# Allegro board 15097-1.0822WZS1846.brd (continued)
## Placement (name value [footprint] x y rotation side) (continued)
C553  SCD1U50V3KX-DL-GP  [C603H35]  137.88 90.2 180 bottom
C554  SCD1U50V3KX-DL-GP  [C603H35]  145.98 108.38 90 bottom
C555  SCD1U50V3KX-DL-GP  [C603H35]  141.23 43.38 180 bottom
C556  SCD1U50V3KX-DL-GP  [C603H35]  93.02 37.49 180 bottom
C557  SCD1U50V3KX-DL-GP  [C603H35]  89.14 37.47 180 bottom
C558  SCD1U50V3KX-DL-GP  [C603H35]  51.9 52.04 0 bottom
C559  SCD1U50V3KX-DL-GP  [C603H35]  36.41 44.93 180 bottom
C560  SCD1U50V3KX-DL-GP  [C603H35]  25.28 67.51 90 bottom
C561  SCD1U50V3KX-DL-GP  [C603H35]  45.63 223.09 270 bottom
C562  SCD1U50V3KX-DL-GP  [C603H35]  72.07 223.27 90 bottom
C563  SCD1U50V3KX-DL-GP  [C603H35]  157.07 71.2 270 bottom
C564  SC1U10V2KX-1DLGP  [C402H22]  163.24 139.82 90 bottom
C565  SC10U10V5KX-2DLGP  [C805H50]  160.67 150.07 0 bottom
C568  SCD1U16V2KX-3DLGP  [C402H22]  161.18 131.35 270 bottom
C569  SC1U10V2KX-1DLGP  [C402H22]  28.74 181.48 270 top
CMCLR2  JOWLE-CON2-5-GP  [A2541WV0-1EX2PA-6T]  147 178 270 top
CONVT1  CLX-CON10-10-GP  [CI1410M1HRL-NH]  25 36.65 270 top
CPU1  APOLLO-LAKE-GP  [BGA1296M3124H56]  83 165 270 top
D1  1SS355-4-GP  [SOD323AKH38]  17.25 202.67 180 top
D2  BAT54A-7-F-2-GP  [SOT23-2D4-312H48]  146.27 192 0 top
D3  BAT54A-7-F-2-GP  [SOT23-2D4-312H48]  100.01 103.4 90 top
D4  BAT54A-7-F-2-GP  [SOT23-2D4-312H48]  124.63 70.92 0 top
D5  BAV99GP-GP  [SOT23-2D4-312H48]  45.4 29.59 90 top
D6  1SS355-4-GP  [SOD323AKH38]  125.53 28.85 180 top
D7  BAS40C-2-GP  [SOT-23-9H44]  136.23 20.62 270 top
D8  1SS355-4-GP  [SOD323AKH38]  130.86 71.19 90 bottom
D9  AZ2015-01H-GP  [SOD523AKH28]  153.39 50.54 90 bottom
D10  BX310F-R1-00000-GP  [D4724AKH44]  30.28 39.29 180 bottom
DCIN1  DC-JACK345-GP  [2DC3115-000111F]  53.25 25.53 90 top
DCIN2  ACES-CONN14G-GP  [88314-077N]  54.75 34 180 top
DIMM1  DDR3-204P-262-GP-U  [AS0A621-J4R6-7H-U]  135.3 158.9 90 top
EC1  SC1KP50V2KX-1DLGP  [C402H22]  120.49 173.36 0 bottom
EC2  SC1KP50V2KX-1DLGP  [C402H22]  119.07 149.56 180 bottom
EC518  SC100P3KV8JN-4-GP  [C1808H87]  65.31 19.3 0 bottom
EC2901  SCD1U50V3KX-DL-GP  [C603H35]  84.92 40.87 270 top
EC8601  SC100P50V2JN-3DLGP  [C402H22]  62.14 131.7 270 bottom
EC8602  SC100P50V2JN-3DLGP  [C402H22]  62.77 130.81 270 bottom
EC8603  SC100P50V2JN-3DLGP  [C402H22]  64.42 131.32 90 top
EC8604  SC100P50V2JN-3DLGP  [C402H22]  64.42 130.18 90 top
EC_DEBUG1  JOWLE-CON2-5-GP  [A2541WV0-1EX2PA-6T]  144.37 87.29 270 top
EMC1  SPRING-166-GP  [SPR6024H64]  102.3 190.7 90 top
EMC2  SPRING-166-GP  [SPR6024H64]  102.3 145.1 270 top
EMC3  SPRING-166-GP  [SPR6024H64]  133.6 197 180 top
EMC4  SPRING-166-GP  [SPR6024H64]  143.05 176.9 270 top
F1  POLYSW-2A6V-7-GP  [POLYSW-2114H30]  17.71 209.35 270 top
F2  FUSE-3A32V-26-GP  [FUSE-1608H22]  42.07 42.04 270 top
F3  POLYSW-1D5A6V-12-GP  [POLYSW-2114H30]  156.63 203.65 270 bottom
F4  POLYSW-1D5A6V-12-GP  [POLYSW-2114H30]  162.71 201.94 90 bottom
F5  FUSE-1D5A6V-11GP  [FUSE-3216H28]  160.75 145.77 180 bottom
F7  POLYSW-1D5A6V-12-GP  [POLYSW-2114H30]  119.69 34.21 0 bottom
F8  POLYSW-1D5A6V-12-GP  [POLYSW-2114H30]  24.83 7.44 270 bottom
FANC3  FOX-CON4-30-GP  [HF1804H]  14 211 270 top
GPU1  N16S-GM-S-A2-GP  [BGA595M23H83]  83 100 180 top
H1  HOLE237R158-GP  [HOLE237R158]  94.38 192.31 180 top
H2  HOLE237R158-GP  [HOLE237R158]  62.39 165.12 180 top
H3  HOLE237R158-GP  [HOLE237R158]  94.38 137.93 180 top
H4  HOLE237R158-GP  [HOLE237R158]  69 123.75 180 top
H5  HOLE237R158-GP  [HOLE237R158]  94.39 76.25 180 top
H6  GEN8D5X8R5X4D5-8-F-A-GP  [GEN8D5X8R5X4D5-8-F-A]  165 225 270 top
H7  GEN315R138-8-F-A-1-GP  [GEN315R138-8-F-A-1]  5 160 180 top
H9  GEN8D5X8R5X4D5-8-F-A-GP  [GEN8D5X8R5X4D5-8-F-A]  25 49.15 0 top
H10  GEN315R178-8-F-A-3-GP  [GEN315R178-8-F-A-1]  165 20 180 top
H11  GEN315R138-8-F-A-2-S-GP  [GEN315R138-8-F-A-2-S]  172.5 64.43 180 top
HDD1  SKT-SATA7P-184-GP-U  [15-02070-5A61-A]  12 142 270 top
HDMI1  SKT-HDMI22-12-GP  [SKT-HDMI22-150077]  113.99 37.03 270 top
HDMI2  ARG-CON20-GP  [LVDFH-02004-TP00]  118.69 37.07 270 top
HS6  STF256R109H99-GP  [STF256R109H99]  144.25 214 180 top
IRMTCN1  ACES-CON4-37-GP  [88459-047N]  49.13 169.11 0 top
JMP1  PIN-CONN6A-S3-GP  [21S-92-03GB16]  148 171 270 top
L1  MCB1005S121FBP-GP  [L402H24]  160.47 191.1 90 top
L2  FILTER-4P-123-GP  [L125100-4P-1H36]  20.05 139.73 0 top
L3  FILTER-4P-123-GP  [L125100-4P-1H36]  20.05 137.48 0 top
L4  FILTER-4P-123-GP  [L125100-4P-1H36]  165.72 119.35 180 top
L5  FILTER-4P-123-GP  [L125100-4P-1H36]  165.9 117.09 180 top
L6  FILTER-4P-123-GP  [L125100-4P-1H36]  166.15 97.16 180 top
L7  FILTER-4P-123-GP  [L125100-4P-1H36]  166.15 94.87 180 top
L8  IND-33UH-85-GP  [L8080-6020H158]  34.82 38.66 270 top
L9  MHC1608S221NBP-GP  [L603H38]  152.76 37.97 90 top
L10  MCB1005S121FBP-GP  [L402H24]  86.29 33.48 270 top
L11  MCB1005S121FBP-GP  [L402H24]  84.26 33.45 270 top
L12  HCB2012KF-601T20-GP  [L20125H42]  143.9 23.6 0 top
L13  HCB2012KF-601T20-GP  [L20125H42]  145.93 23.6 0 top
L14  HCB2012KF-601T20-GP  [L20125H42]  148.12 22.78 0 top
L15  HCB2012KF-601T20-GP  [L20125H42]  150.27 22.78 0 top
L16  BLM15BD102SN1D-GP  [L402H22]  47.73 22.07 0 top
L17  MHC1608S300QBP-GP  [L603H38]  74.02 116.31 180 bottom
L19  HCB1608KF-800T30-GP  [L603H38]  38.02 105.52 270 bottom
L20  IND-2D2UH-250-GP-U  [L3030-2709H41]  31.83 104.65 0 bottom
L21  MHC1608S181NBP-GP  [L603H38]  96.12 102.35 180 bottom
L22  MHC1608S300QBP-GP  [L603H38]  96.16 98.57 180 bottom
L23  HCB1608KF-800T30-GP  [L603H38]  32.71 78.28 270 bottom
L24  HCB1608KF-800T30-GP  [L603H38]  153.4 55.12 90 bottom
L25  MCB1005S121FBP-GP  [L402H24]  157.64 41.45 270 bottom
L26  -  [0R0805-PAD]  119.82 37.77 180 bottom
LED1  LED-O-23-GP  [LED1608AKH30]  170.07 91.45 180 top
LOUT1  AUDIO-JK419-GP  [JAC331-0140A8B-9H]  76.93 37.66 90 top
LPC1  FOX-CONN14A-S1-GP  [HL5507F]  109.63 74.7 0 top
LVDS1  ACES-CON30-21-GP  [50524-0300N-001]  36.8 95 270 top
MEMCD1  SKT-SDCARD-52-GP  [156-5101902601]  174.65 144.79 90 top
NGFF1  SKT-MINI67P-3-GP-U1  [2199230-7]  116 214 270 top
NOREF  -  []  -10 0 0 top
NOREF#2  *  [unnamed#2]  171.63 8.45 0 top
NOREF#3  *  [unnamed#2]  167.76 125.36 0 top
NOREF#4  -  [unnamed#2]  183.93 6.22 0 top
NOREF#5  -  [unnamed#2]  152.94 226.06 0 top
NOREF#6  -  []  66.2 224.16 0 top
NOREF#7  *  [unnamed#2]  164.75 61.21 0 top
NOREF#8  -  [unnamed#2]  171.63 4.95 0 top
NOREF#9  -  [unnamed#2]  11.57 4.95 0 top
NOREF#10  *  [unnamed#2]  17.11 224.63 0 top
NOREF#11  -  [unnamed#2]  178.22 223.03 0 top
NOREF#12  -  []  0 103.25 0 top
NOREF#13  -  [unnamed#2]  6 10.67 0 top
NOREF#14  *  [unnamed#2]  156.32 223.72 0 top
NOREF#15  -  []  -10 0 0 top
NOREF#16  -  []  -10 0 0 top
NOREF#17  *  [unnamed#2]  65.72 5.8 0 top
NOREF#18  *  [unnamed#2]  178.33 217.98 0 top
NOREF#19  *  [unnamed#2]  5.05 6.01 0 top
NOREF#20  *  [unnamed#2]  104.17 47.88 0 top
NOREF#21  -  [unnamed#2]  94.14 12.32 0 top
NOREF#22  -  []  55.65 130.04 0 top
NOREF#23  *  [unnamed#2]  54.8 145.08 0 top
NOREF#24  -  [unnamed#2]  185.45 223.65 0 top
NOREF#25  -  []  135.03 219.33 0 top
NOREF#26  -  []  -10 0 0 top
NOREF#27  -  []  37.07 131.88 0 top
NOREF#28  *  [unnamed#2]  155.99 17.12 0 top
NOREF#29  *  [unnamed#2]  65.72 5.8 180 bottom
NOREF#30  *  [unnamed#2]  54.8 145.08 180 bottom
NOREF#31  -  []  114.08 175.34 90 bottom
NOREF#32  -  []  178.58 28.52 90 bottom
NOREF#33  *  [unnamed#2]  10.83 219.71 180 bottom
NOREF#34  *  [unnamed#2]  5.05 6.01 180 bottom
NOREF#35  *  [unnamed#2]  149.26 8.26 180 bottom
NOREF#36  *  [unnamed#2]  178.33 217.98 180 bottom
NOREF#37  *  [unnamed#2]  156.32 223.72 180 bottom
NOREF#38  *  [unnamed#2]  171.63 8.45 180 bottom
NOREF#39  *  [unnamed#2]  73.07 79.1 180 bottom
ODD1  SKT-SATA7P-184-GP-U  [15-02070-5A61-A]  8.35 177 270 top
PC1  SCD1U10V2KX-4DLGP  [C402H22]  7.42 222.74 270 top
PC2  SCD1U10V2KX-4DLGP  [C402H22]  7.44 219.28 270 top
PC3  SCD01U50V2KX-1DLGP  [C402H22]  53.89 218.59 180 top
PC4  SCD1U25V2KX-1-DL-GP  [C402H22]  53.89 216.6 0 top
PC5  SC1U10V2KX-1DLGP  [C402H22]  61.4 216.39 90 top
PC6  SC1U10V2KX-1DLGP  [C402H22]  55.68 215.62 270 top
PC7  SC33P50V2JN-3DLGP  [C402H22]  53.36 212.96 180 top
PC8  SC470P50V2KX-3DLGP  [C402H22]  54.35 212.96 180 top
PC9  SCD1U25V2KX-1-DL-GP  [C402H22]  67.44 211.56 270 top
PC10  SC470P50V2KX-3DLGP  [C402H22]  52.9 210.35 90 top
PC11  SC15P50V2JN-L-GP  [C402H22]  54.4 210.2 180 top
PC12  SC220P50V2KX-3DLGP  [C402H22]  65.59 209.19 90 top
PC13  SC1KP50V2KX-1DLGP  [C402H22]  60.32 208.99 0 top
PC14  SC470P50V2KX-3DLGP  [C402H22]  52.4 207.91 180 top
PC15  SC15P50V2JN-L-GP  [C402H22]  62.19 207.49 180 top
PC16  SC470P50V2KX-3DLGP  [C402H22]  54.89 206.81 90 top
PC17  SC10U25V5KX-DL-GP  [C805H58]  41.28 206.2 270 top
PC18  SCD015U50V3KX-GP  [C603]  61.43 205.88 270 top
PC19  SC10U25V5KX-DL-GP  [C805H58]  41.29 204.23 270 top
PC20  SC1KP50V2KX-1DLGP  [C402H22]  37.45 200.41 270 top
PC21  SC10U10V5KX-2DLGP  [C805H50]  23.91 199.77 270 top
PC22  SCD01U16V2KX-3GP  [C402H22]  27.08 198.12 90 top
PC23  SC10U10V5KX-2DLGP  [C805H50]  23.91 197.61 270 top
PC24  SC22P50V2JN-4GP  [C402H22]  158.01 193 180 top
PC25  SC10U10V5KX-2DLGP  [C805H50]  22.97 188.82 0 top
PC26  SC1U50V3KX-1-GP  [C603H36]  25.43 187.2 270 top
PC27  SCD1U10V2KX-4DLGP  [C402H22]  30.47 184.26 90 top
PC28  SC100P50V2JN-3DLGP  [C402H22]  25.48 183.21 270 top
PC29  SCD1U10V2KX-4DLGP  [C402H22]  31.4 182.8 180 top
PC30  SC470P50V2KX-3DLGP  [C402H22]  23.99 181.14 270 top
PC31  SC22U6D3V5MX-2DLGP  [C805H54]  41.15 180.39 180 top
PC32  SC22U6D3V5MX-2DLGP  [C805H54]  43.29 180.38 180 top
PC33  SC1U10V2KX-1DLGP  [C402H22]  24.41 179.07 270 top
PC34  SC10U10V5KX-2DLGP  [C805H50]  27.3 175.75 90 top
PC35  SC10U10V5KX-2DLGP  [C805H50]  27.3 173.74 90 top
PC36  SC22U6D3V5MX-2DLGP  [C805H54]  41.11 173.53 0 top
PC37  SCD1U16V2KX-3DLGP  [C402H22]  42.96 173.48 0 top
PC38  SC1KP50V3KX-DLGP  [C603H36]  29.82 173.09 180 top
PC39  SC22P50V2JN-4DLGP  [C402H22]  32.42 169.04 0 top
PC40  SCD1U10V2KX-4DLGP  [C402H22]  35.59 169.04 180 top
PC41  SCD1U10V2KX-4DLGP  [C402H22]  36.61 169.04 180 top
PC42  SC470P50V2KX-3DLGP  [C402H22]  29.6 167.88 270 top
PC43  SC1U10V2KX-1DLGP  [C402H22]  153.69 167.39 180 top
PC44  SC22U6D3V5MX-2DLGP  [C805H54]  47.1 166.65 90 top
PC45  SC1U10V2KX-1DLGP  [C402H22]  29.6 165.93 270 top
PC46  SC22U6D3V5MX-2DLGP  [C805H54]  47.1 164.67 90 top
PC47  SCD1U16V2KX-3DLGP  [C402H22]  47.07 163.22 270 top
PC48  SC10U10V5KX-2DLGP  [C805H50]  32.35 162.49 90 top
PC49  SC10U10V5KX-2DLGP  [C805H50]  32.35 160.46 90 top
PC50  SC1KP50V3KX-DLGP  [C603H36]  34.83 159.64 180 top
PC51  SC470P50V2KX-3DLGP  [C402H22]  25.46 153.21 270 top
PC54  SC22U6D3V5MX-2DLGP  [C805H54]  43.57 152.58 180 top
PC55  SC22U6D3V5MX-2DLGP  [C805H54]  45.52 152.58 180 top
PC56  SC22U6D3V5MX-2DLGP  [C805H54]  47.51 152.58 180 top
PC57  SCD1U16V2KX-3DLGP  [C402H22]  49.03 152.65 0 top
PC58  SCD1U16V2KX-3DLGP  [C402H22]  32.98 154.64 180 top
PC59  SCD1U10V2KX-4DLGP  [C402H22]  30.97 154.66 180 top
PC60  SC1KP50V2KX-1DLGP  [C402H22]  151.29 149.61 0 top
PC61  SC10U25V5KX-DL-GP  [C805H58]  151.44 147.65 90 top
PC62  SC1U10V2KX-1DLGP  [C402H22]  25.43 151.05 270 top
PC63  SC100P50V2JN-3DLGP  [C402H22]  25.46 154.13 90 top
PC64  SC10U10V5KX-2DLGP  [C805H50]  29.71 148.06 90 top
PC65  SC1KP50V2KX-1DLGP  [C402H22]  31.55 144.68 270 top
PC66  SC10U25V5KX-DL-GP  [C805H58]  151.44 145.67 90 top
PC67  SC10U10V5KX-2DLGP  [C805H50]  29.72 146.1 90 top
PC68  SCD1U50V3KX-DL-GP  [C603H35]  153.47 139.29 0 top
PC69  SC10U10V5KX-2DLGP  [C805H50]  149.49 138.56 270 bottom
PC70  SC10U10V5KX-2DLGP  [C805H50]  146.95 137.34 270 top
PC71  SC10U10V5KX-2DLGP  [C805H50]  146.46 135.13 270 top
PC72  SC1U10V2KX-1DLGP  [C402H22]  155.43 135.02 180 top
PC73  SC1U10V2KX-1DLGP  [C402H22]  155.44 132.23 0 top
PC74  SC18P50V2JN-1-GP  [C402H22]  145.34 132.15 0 top
PC75  SCD1U16V2KX-L-GP  [C402H22]  152.03 129.62 270 top
PC76  SCD1U10V2KX-4DLGP  [C402H22]  115.44 119.35 270 top
PC77  SC10U10V5KX-2DLGP  [C805H50]  110.43 116.09 0 top
PC78  SCD1U16V2KX-3DLGP  [C402H22]  120.33 113.51 180 top
PC79  SC10U10V5KX-2DLGP  [C805H50]  107.86 112.24 180 top
PC80  SC100P50V2JN-3GP  [C402H22]  110.45 111.38 180 top
PC81  SC1U50V3KX-1-GP  [C603H36]  121.04 110.44 90 top
PC82  SC10U10V5KX-2DLGP  [C805H50]  107.93 108.56 0 top
PC83  SC10U10V5KX-2DLGP  [C805H50]  109.96 108.53 0 top
PC84  SC22U6D3V5MX-2DLGP  [C805H54]  113.9 104.83 180 top
PC85  SC1500P50V3KX-DLGP  [C603H36]  134.17 98.04 90 top
PC86  SC10U25V5KX-DL-GP  [C805H58]  136.51 97.23 180 top
PC87  SC1KP50V2KX-1DLGP  [C402H22]  121.39 87.55 270 top
PC88  SCD01U25V2KX-L1-GP  [C402H22]  125.46 87.05 180 top
PC89  SC1U10V2KX-1DLGP  [C402H22]  126.35 87.05 180 top
PC90  SC2700P50V2KX-1-DL-GP  [C402H22]  121.45 84.96 180 top
PC91  SCD1U50V3KX-DL-GP  [C603H35]  133.28 84.89 270 top
PC92  SC5600P50V3KX-DL-GP  [C603H36]  118.4 84.71 180 top
PC93  SCD1U16V2KX-3DLGP  [C402H22]  121.45 83.06 0 top
PC94  SC4D7U6D3V3KX-DLGP  [C603H36]  132.65 81.43 270 top
PC95  SC22P50V2JN-4DLGP  [C402H22]  122.84 80.26 270 top
PC96  SC33P50V2JN-3DLGP  [C402H22]  118.52 79.6 180 top
PC97  SC100P50V2JN-3DLGP  [C402H22]  121.32 79.6 0 top
PC98  SCD1U16V2KX-3DLGP  [C402H22]  124.49 77.34 0 top
PC99  SC1U50V3KX-1-GP  [C603H36]  127.08 77.44 270 top
PC100  SCD1U50V3KX-DL-GP  [C603H35]  35.8 74.98 180 top
PC101  SCD1U50V3KX-DL-GP  [C603H35]  37.03 74.98 180 top
PC102  SC2200P50V2KX-2DLGP  [C402H22]  34.78 74.67 180 top
PC103  SC10U25V5KX-DL-GP  [C805H58]  31.4 74.63 180 top
PC104  SC10U25V5KX-DL-GP  [C805H58]  33.35 74.62 180 top
PC105  SC10U25V5KX-DL-GP  [C805H58]  39.42 74.62 90 top
PC106  SC1U50V3KX-1-GP  [C603H36]  57.08 73.43 180 top
PC107  SC1KP50V2KX-1DLGP  [C402H22]  42.26 72.68 180 top
PC108  SC1KP50V2KX-1DLGP  [C402H22]  74.89 71.07 270 top
PC109  SCD1U50V3KX-DL-GP  [C603H35]  62.26 64.39 0 top
PC110  SCD1U16V2KX-3DLGP  [C402H22]  60.5 63.63 270 top
PC111  SCD1U16V2KX-3DLGP  [C402H22]  65.82 62.1 0 top
PC112  SC22P50V2JN-4DLGP  [C402H22]  57.39 61.14 0 top
PC113  SC4D7U6D3V3KX-DLGP  [C603H36]  68.69 59.35 90 top
PC114  SCD1U50V3KX-DL-GP  [C603H35]  43.48 59.01 90 top
PC115  SC1U10V2KX-1DLGP  [C402H22]  97.63 58.8 90 top
PC116  SC22P50V2JN-4DLGP  [C402H22]  57.13 56.96 180 top
PC117  SC1U10V2KX-1DLGP  [C402H22]  96.9 56.87 180 top
PC118  SCD1U50V3KX-DL-GP  [C603H35]  66.07 56.46 90 top
PC119  SCD1U16V2KX-3DLGP  [C402H22]  58.57 54.71 270 top
PC120  SC1U10V2KX-1DLGP  [C402H22]  44.69 54.48 180 top
PC121  SCD1U50V3KX-DL-GP  [C603H35]  61.25 53.87 0 top
PC122  SC470P50V2KX-3DLGP  [C402H22]  39.29 53.46 0 top
PC123  SCD1U25V2KX-1-DL-GP  [C402H22]  37.8 52.54 90 top
PC124  SC10U25V5KX-DL-GP  [C805H58]  37.9 51.1 90 top
PC125  SC1U50V3KX-1-GP  [C603H36]  65.11 30.62 90 top
PC126  SC470P50V2KX-3DLGP  [C402H22]  152.26 21.41 270 top
PC127  SCD1U50V3KX-DL-GP  [C603H35]  62.9 221.36 0 bottom
PC128  SCD1U50V3KX-DL-GP  [C603H35]  58.45 221.11 180 bottom
PC129  SC10U25V5KX-DL-GP  [C805H58]  76.49 217.3 270 bottom
PC130  SCD047U25V2KX-GP  [C402H22]  53.02 215.95 0 bottom
PC131  SC10U25V5KX-DL-GP  [C805H58]  76.46 215.35 270 bottom
PC132  SCD01U50V2KX-1DLGP  [C402H22]  54.26 214.76 180 bottom
PC133  SC1KP50V2KX-1DLGP  [C402H22]  77.52 212.98 0 bottom
PC134  SC1U10V2KX-1DLGP  [C402H22]  127.29 212.47 90 bottom
PC135  SCD015U25V2KX-DLGP  [C402H22]  62.9 207.52 270 bottom
PC136  SC1500P50V2KX-2-DL-GP  [C402H22]  62.9 206.63 270 bottom
PC137  SC1KP50V2KX-1GP  [C402H22]  56.6 206.12 0 bottom
PC138  SC1KP50V2KX-1DLGP  [C402H22]  58.63 206.1 0 bottom
PC139  SC10U25V5KX-DL-GP  [C805H58]  41.28 206.2 90 bottom
PC140  SC2200P50V2KX-2DLGP  [C402H22]  54.77 205.61 270 bottom
PC141  SCD1U25V2KX-1-DL-GP  [C402H22]  68.49 205.49 270 bottom
PC142  SC1KP50V2KX-1DLGP  [C402H22]  54.77 204.72 90 bottom
PC143  SC1KP50V2KX-1DLGP  [C402H22]  58.08 204.69 270 bottom
PC144  SC1U50V5KX-DL-GP  [C805H54]  76.12 193.07 90 bottom
PC145  SC22U6D3V5MX-2DLGP  [C805H54]  71.3 192.59 90 bottom
PC146  SCD1U25V2KX-1-DL-GP  [C402H22]  29.75 188.72 0 bottom
PC147  SC22P50V2GN-GP  [C402H22]  29.75 186.69 180 bottom
PC148  SCD1U16V2KX-3DLGP  [C402H22]  27.47 186.69 180 bottom
PC149  SC22U6D3V5MX-2DLGP  [C805H54]  84.21 183.87 270 bottom
PC150  SC22U6D3V5MX-2DLGP  [C805H54]  96.32 182.5 0 bottom
PC151  SC22U6D3V5MX-2DLGP  [C805H54]  106.84 182.47 0 bottom
PC152  SC22U6D3V5MX-2DLGP  [C805H54]  90.89 181.61 270 bottom
PC153  SC22U6D3V5MX-2DLGP  [C805H54]  90.25 179.45 270 bottom
PC154  SC22U6D3V5MX-2DLGP  [C805H54]  140.17 172.53 270 bottom
PC155  SC1U10V2KX-1DLGP  [C402H22]  89.39 172.34 270 bottom
PC156  SC22U6D3V5MX-2DLGP  [C805H54]  140.17 170.53 270 bottom
PC157  SC1U10V2KX-1DLGP  [C402H22]  88.79 168.98 270 bottom
PC158  SC22U6D3V5MX-2DLGP  [C805H54]  140.17 168.42 270 bottom
PC159  SC22U6D3V5MX-2DLGP  [C805H54]  96.22 161.72 180 bottom
PC160  SC1U10V2KX-1DLGP  [C402H22]  86.93 159.19 90 bottom
PC161  SC22U6D3V5MX-2DLGP  [C805H54]  94 158.94 270 bottom
PC162  SC22U6D3V5MX-2DLGP  [C805H54]  74.94 158.34 180 bottom
PC163  SC22U6D3V5MX-2DLGP  [C805H54]  72.07 157.57 180 bottom
PC164  SC22U6D3V5MX-2DLGP  [C805H54]  92.35 156.08 0 bottom
PC165  SC22U6D3V5MX-2DLGP  [C805H54]  140.42 153.54 270 bottom
PC166  SC22U6D3V5MX-2DLGP  [C805H54]  90.65 151.59 180 bottom
PC167  SC22U6D3V5MX-2DLGP  [C805H54]  88.7 151.59 180 bottom
PC168  SC22U6D3V5MX-2DLGP  [C805H54]  140.42 151.54 270 bottom
PC169  SC22U6D3V5MX-2DLGP  [C805H54]  78.2 148.19 90 bottom
PC170  SC10U25V5KX-DL-GP  [C805H58]  151.44 147.65 270 bottom
PC171  SC22U6D3V5MX-2DLGP  [C805H54]  88.4 147.29 90 bottom
PC172  SCD047U25V2KX-GP  [C402H22]  149.99 134.01 0 bottom
PC173  SC10U25V5KX-DL-GP  [C805H58]  138.44 97.23 0 bottom
PC174  SC10U25V5KX-DL-GP  [C805H58]  136.51 97.23 0 bottom
PC175  SC10P50V2JN-4DLGP  [C402H22]  45.45 71.87 0 bottom
PC176  SC10P50V2JN-4DLGP  [C402H22]  45.45 69.94 180 bottom
PC177  SC10U25V5KX-DL-GP  [C805H58]  72.77 67.05 0 bottom
PC178  SC10U25V5KX-DL-GP  [C805H58]  70.81 67.03 0 bottom
PC179  SCD01U50V2KX-1DLGP  [C402H22]  53.63 63.88 270 bottom
PC180  SCD1U50V3KX-DL-GP  [C603H35]  46.35 63.8 0 bottom
PC181  SCD1U50V3KX-DL-GP  [C603H35]  45.11 63.8 0 bottom
PC182  SCD1U50V3KX-DL-GP  [C603H35]  45.89 61.85 270 bottom
PC183  SC220P50V2KX-3DLGP  [C402H22]  53.63 61.72 270 bottom
PC184  SC470P50V2KX-3DLGP  [C402H22]  33.35 61.56 270 bottom
PC185  SC4D7U6D3V3KX-DLGP  [C603H36]  60.38 61.34 270 bottom
PC186  SCD47U25V3KX-1-DL-GP  [C603H36]  43.57 60.55 0 bottom
PC187  SCD1U25V2KX-1-DL-GP  [C402H22]  49.98 53.2 0 bottom
PC188  SCD1U25V2KX-1-DL-GP  [C402H22]  46.88 53.2 0 bottom
PC189  SCD1U50V3KX-DL-GP  [C603H35]  48.44 51.57 270 bottom
PC190  SC10U25V5KX-DL-GP  [C805H58]  37.89 51.09 270 bottom
PC191  SCD1U25V3KX-DLGP  [C603H36]  63.53 33.12 270 bottom
PC192  SCD1U25V3KX-DLGP  [C603H36]  63.53 31.93 270 bottom
PC193  SCD1U50V3KX-DL-GP  [C603H35]  63.53 29.59 90 bottom
PC194  SC1U10V2KX-1DLGP  [C402H22]  29.03 9.98 180 bottom
PC195  SC22U6D3V5MX-2DLGP  [C805H54]  47.1 161.8 270 bottom
PC196  SC10U25V5KX-DL-GP  [C805H58]  72.98 54.53 0 bottom
PC197  SC10U25V5KX-DL-GP  [C805H58]  41.29 204.23 90 bottom
PC198  SCD1U25V2KX-1-DL-GP  [C402H22]  32.01 186.87 270 top
PCB1  SC10U25V5KX-DL-GP  [C805H58]  72.98 54.53 180 top
PCT1  SC10U25V5KX-DL-GP  [C805H58]  70.95 54.53 180 top
PCT2  SC1KP50V2KX-1DLGP  [C402H22]  75.66 59.1 270 top
PD1  1N4148WS-7-F-GP  [SOD323AKH42]  54.74 70.64 90 top
PD2  CES520-GP  [SOD523AKH28]  43.21 55.63 180 top
PD3  P6SBMJ24AGP-GP  [D5436AKH97]  64.46 25.82 270 top
PG1  GAP-CLOSE-PWR-6-GP  [GAP-CLOSE-PWR]  48.43 192.85 180 top
PG2  GAP-CLOSE-PWR-6-GP  [GAP-CLOSE-PWR]  53.95 192.83 0 top
PG3  GAP-CLOSE-PWR-3-GP  [GAP-CLOSE-PWR-3]  92.12 71.07 270 top
PG4  GAP-CLOSE-PWR-3-GP  [GAP-CLOSE-PWR-3]  40.65 65.77 180 top
PG5  GAP-CLOSE-PWR-3-GP  [GAP-CLOSE-PWR-3]  40.65 64.76 180 top
PG6  GAP-CLOSE-PWR-3-GP  [GAP-CLOSE-PWR-3]  68.03 57.48 270 top
PG7  GAP-CLOSE-PWR-3-GP  [GAP-CLOSE-PWR-3]  93.78 48.97 90 top
PG8  GAP-CLOSE-PWR-3-GP  [GAP-CLOSE-PWR-3]  53.3 48.15 90 top
PG9  GAP-CLOSE-PWR-3-GP  [GAP-CLOSE-PWR-3]  51.54 48.13 90 top
PG10  GAP-CLOSE-PWR-3-GP  [GAP-CLOSE-PWR-3]  65.46 207.08 270 bottom
PG11  GAP-CLOSE-PWR-3-GP  [GAP-CLOSE-PWR-3]  64.45 207.08 270 bottom
PG12  GAP-CLOSE-PWR-3-GP  [GAP-CLOSE-PWR-3]  76.24 205.2 90 bottom
PG13  0R2J-2-GP  [R402H16]  59.7 203.72 0 bottom
PG14  GAP-CLOSE-PWR-3-GP  [GAP-CLOSE-PWR-3]  58.07 203.71 180 bottom
PG15  GAP-CLOSE-PWR-3-GP  [GAP-CLOSE-PWR-3]  55.29 203.49 90 bottom
PG16  GAP-CLOSE-PWR-3-GP  [GAP-CLOSE-PWR-3]  54.28 203.49 90 bottom
PG17  GAP-CLOSE-PWR-3-GP  [GAP-CLOSE-PWR-3]  76.24 201.8 270 bottom
PG18  GAP-CLOSE-PWR-3-GP  [GAP-CLOSE-PWR-3]  57.82 61.37 0 bottom
PGT1  GAP-CLOSE-PWR-3-GP  [GAP-CLOSE-PWR-3]  94.39 70.99 270 top
PL1  IND-D22UH-31-GP  [L112100-2230H158]  51.2 192.84 90 top
PL2  IND-1D5UH-53-GP-U  [L686647-127318H119]  35.61 177.4 90 top
PL3  IND-1D5UH-53-GP-U  [L686647-127318H119]  40.7 163.92 90 top
PL4  IND-1D5UH-53-GP-U  [L686647-127318H119]  156.04 160.6 180 top
PL5  IND-1D5UH-53-GP-U  [L686647-127318H119]  38.03 150.6 90 top
PL6  IND-D36UH-19-GP  [L115100-2H158]  120.18 97.03 270 top
PL7  IND-2D2UH-122-GP-U  [L686647-127318H119]  83.65 66.19 90 top
PL8  IND-2D2UH-122-GP-U  [L686647-127318H119]  83.9 54.48 270 top
PL9  IND-D47UH-33-GP-U  [L686647-127318H119]  76.23 203.47 180 bottom
PL10  MLVS0402M04-GP-U  [L402H24]  46.4 71.86 0 bottom
PL11  MLVS0402M04-GP-U  [L402H24]  46.4 69.96 180 bottom
PL12  IND-5D6UH-45-GP-U  [L686647-127318H119]  38.17 62.82 0 bottom
PL13  MLVS0402M04-GP-U  [L402H24]  33.35 62.58 270 bottom
PQ1  NTMFS4C10NT1G-GP  [PTDS08-1H44]  46.27 204.17 0 top
PQ2  NTMFS4C06NT1G-GP  [PTDS08-1H44]  41.35 195.74 270 top
PQ3  NTMFS4C06NT1G-GP  [PTDS08-1H44]  41.37 189.37 270 top
PQ4  AON7410-GP  [PPAK-8P-3232H36]  148.12 151.99 180 top
PQ5  AON7506-GP  [PPAK-8P-3232H36]  154.72 153.47 0 top
PQ6  2N7002KDW-GP  [SOT-363H44]  54.54 73.25 270 top
PQ7  LMBT3906LT1G-1-GP  [SOT23CBE2D4H44]  50.76 71.98 90 top
PQ8  2N7002KDW-GP  [SOT-363H44]  49.49 67.92 270 top
PQ9  AON7506-GP  [PPAK-8P-3232H36]  77.27 67.77 270 top
PQ10  2N7002K-2-GP  [SOT23DGS2D4H44]  54.26 66.67 0 top
PQ11  AON7410-GP  [PPAK-8P-3232H36]  75.75 63.15 90 top
PQ12  2N7002A-7-GP  [SOT23DGS2D4H48]  53.93 62.69 270 top
PQ13  NTJD512NT1G-GP  [SOT-363H44]  47.28 40.13 0 top
PQ14  LMUN5212T1G-GP  [SOT323CBE2D2H40]  69.89 37.47 180 top
PQ15  PDTA124EU-1-GP  [SOT323CBE2D2H44]  69.91 29.89 90 top
PQ16  NTMFS4C10NT1G-GP  [PTDS08-1H44]  46.29 204.19 180 bottom
PQ17  2N7002K-2-GP  [SOT23DGS2D4H44]  49.43 65.59 90 bottom
PQ18  AON7410-GP  [PPAK-8P-3232H36]  75.98 52.02 90 top
PQ19  2N7002A-7-GP  [SOT23DGS2D4H48]  55.53 56.01 270 bottom
PQ20  AON7506-GP  [PPAK-8P-3232H36]  77.48 56.44 270 top
PR1  1KR2F-3-GP  [R402H16]  51.43 218.94 90 top
PR2  2D2R5J-1-GP  [R805H24]  65.35 217.86 90 top
PR3  19K6R2F-GP  [R402H16]  51.01 217.45 180 top
PR4  0R0402-PAD-1-GP  [0R0402-PAD]  52.48 217.04 90 top
PR5  -  [0R0805-PAD]  41.16 216.92 0 top
PR6  -  [0R0805-PAD]  43.09 216.92 0 top
PR7  -  [0R0805-PAD]  45.02 216.92 0 top
PR8  -  [0R0805-PAD]  46.95 216.92 0 top
PR9  84K5R3F-L-GP  [R603H22]  52.3 214.92 90 top
PR10  2D2R3-1-U-GP  [R603H22]  57.67 214.88 180 top
PR11  487KR2F-2-GP  [R402H16]  51.92 213.43 270 top
PR12  75KR2F-GP  [R402H16]  51.93 212.39 90 top
PR13  22K1R2F-L-GP  [R402H16]  65.54 211.51 90 top
PR14  20KR2F-L-GP  [R402H16]  52.82 211.36 270 top
PR15  102KR2F-GP  [R402H16]  65.6 210.14 90 top
PR16  1KR2F-3-GP  [R402H16]  57.43 210.03 0 top
PR17  10KR2F-2-GP  [R402H16]  156.82 209.54 270 top
PR18  1KR2F-3-GP  [R402H16]  55.47 209.54 180 top
PR19  6K49R2F-1-GP  [R402H16]  52.9 209.39 270 top
PR20  28KR2F-GP  [R402H16]  59.32 208.99 0 top
PR21  20KR2F-L-GP  [R402H16]  57.86 208.55 270 top
PR22  84K5R2F-GP  [R402H16]  54.43 208.24 0 top
PR23  49D9R2F-GP  [R402H16]  53.4 207.92 0 top
PR24  1K5R2F-2-GP  [R402H16]  59.52 206.32 180 top
PR25  NTC-100K-11-GP-U  [NTC-402H24-U]  49.94 206.12 0 top
PR26  29K4R2F-GP  [R402H16]  54.92 205.79 90 top
PR27  10KR2F-2-GP  [R402H16]  147.71 205.79 90 top
PR28  10KR2F-2-GP  [R402H16]  148.17 204.19 180 top
PR29  1R5J-2-GP  [R805H24]  50.59 202.07 0 top
PR30  2D2R5J-1-GP  [R805H24]  40.84 200.43 270 top
PR31  -  [0R0805-PAD]  27.59 199.77 270 top
PR32  10KR2J-3-GP  [R402H16]  50.58 199.34 0 top
PR33  NTC-220K-5-GP-U  [NTC-402H24-U]  52.61 198.88 90 top
PR34  10KR2F-2-GP  [R402H16]  28.86 197.61 0 top
PR35  12K7R2F-GP  [R402H16]  27.08 197.1 90 top
PR36  1KR2J-1-GP  [R402H16]  30.52 190.88 0 top
PR37  10KR2J-3-GP  [R402H16]  27.47 186.82 180 top
PR38  47KR2J-2-GP  [R402H16]  28.48 186.82 0 top
PR39  10KR2J-3-GP  [R402H16]  32.42 182.8 0 top
PR40  0R2J-2-GP  [R402H16]  30.18 182.88 180 top
PR41  18KR2F-GP  [R402H16]  24 182.58 180 top
PR42  1KR2F-3-GP  [R402H16]  51.98 178.69 90 top
PR43  2D2R5J-1-GP  [R805H24]  23.56 177.58 90 top
PR44  -  [0R0805-PAD]  44.36 177.55 90 top
PR45  -  [0R0603-PAD]  22.1 175.78 270 top
PR46  -  [0R0805-PAD]  44.36 175.51 90 top
PR47  -  [0R0603-PAD]  22.09 174.44 270 top
PR48  2D2R5J-1-GP  [R805H24]  32.27 172.57 270 top
PR49  0R0402-PAD-2-GP  [0R0402-PAD-1]  33.43 169.04 180 top
PR50  1KR2J-1-GP  [R402H16]  34.58 169.04 0 top
PR51  10KR2J-3-GP  [R402H16]  37.63 169.04 0 top
PR52  18KR2F-GP  [R402H16]  29.62 168.91 90 top
PR53  -  [0R0603-PAD]  27.1 166.99 180 top
PR54  -  [0R0603-PAD]  25.72 166.97 180 top
PR55  2D2R5J-1-GP  [R805H24]  28.81 164.46 90 top
PR56  169R2F-GP  [R402H16]  53.5 163.83 90 top
PR57  -  [0R0805-PAD]  47.07 161.8 90 top
PR58  2D2R5J-1-GP  [R805H24]  37.34 159.05 270 top
PR60  18KR2F-GP  [R402H16]  25.43 152.12 90 top
PR61  -  [0R0805-PAD]  25.41 147.47 270 top
PR62  2D2R5J-1-GP  [R805H24]  151.43 153.56 0 top
PR63  10KR2J-3-GP  [R402H16]  31.99 154.66 0 top
PR64  1KR2J-1-GP  [R402H16]  29.9 154.66 0 top
PR65  2D2R5J-1-GP  [R805H24]  25.41 149.5 270 top
PR67  51KR2F-L-GP  [R402H16]  25.46 156.16 270 top
PR69  -  [0R0805-PAD]  48.12 147.47 0 top
PR70  -  [0R0805-PAD]  50.12 147.47 0 top
PR74  2D2R5J-1-GP  [R805H24]  32.52 147.22 0 top
PR75  64K9R2F-1-GP  [R402H16]  25.46 155.14 90 top
PR76  0R2J-2-GP  [R402H16]  28.61 154.66 0 top
PR78  -  [0R0805-PAD]  25.41 145.52 270 top
PR79  -  [0R0805-PAD]  146.95 139.29 90 top
PR80  2D2R5J-1-GP  [R805H24]  151.47 139.06 180 top
PR81  0R0402-PAD-1-GP  [0R0402-PAD]  156.62 133.73 0 top
PR82  -  [0R0402-PAD]  145.93 133.63 270 top
PR83  20KR2F-L-GP  [R402H16]  146.41 132.15 0 top
PR84  -  [0R0402-PAD]  150.45 130.78 90 top
PR85  20KR2F-L-GP  [R402H16]  145.88 130.65 90 top
PR86  100KR2J-1-GP  [R402H16]  154.59 129.92 180 top
PR87  -  [0R0402-PAD]  153.53 129.08 180 top
PR88  47KR2J-2-GP  [R402H16]  121.83 114.17 90 top
PR89  10KR2F-2-GP  [R402H16]  110.4 113.36 180 top
PR90  -  [0R0402-PAD]  121.85 113.08 90 top
PR91  -  [0R0805-PAD]  105.04 111.43 90 top
PR92  3K16R2F-GP  [R402H16]  109.41 111.38 180 top
PR93  -  [0R0805-PAD]  105.04 109.47 90 top
PR94  10KR2J-3-GP  [R402H16]  48.29 107.56 270 top
PR95  10KR2J-3-GP  [R402H16]  51.29 99.19 0 top
PR96  2D2R5J-1-GP  [R805H24]  129.65 98.04 270 top
PR97  10KR2J-3-GP  [R402H16]  97.66 97.79 90 top
PR98  10KR2J-3-GP  [R402H16]  126.33 90.93 270 top
PR99  NTC-100K-12-GP-U  [NTC-402H22-U]  134.79 89.94 270 top
PR100  33KR2F-GP  [R402H16]  123.99 89.15 90 top
PR101  10KR2J-3-GP  [R402H16]  48.31 88.95 270 top
PR102  0R0402-PAD-2-GP  [0R0402-PAD-1]  121.39 88.57 270 top
PR103  2D2R5J-1-GP  [R805H24]  129.98 88.57 180 top
PR104  100R2F-L1-GP-U  [R402H14]  116.45 88.46 0 top
PR105  47KR2J-2-GP  [R402H16]  128.45 87.18 180 top
PR106  -  [0R0402-PAD]  127.36 87.17 0 top
PR107  1KR2J-1-GP  [R402H16]  124.04 87.05 270 top
PR108  2D2R5J-1-GP  [R805H24]  132.72 86.46 90 top
PR109  20KR2F-L-GP  [R402H16]  120.05 85.98 270 top
PR110  18KR2F-GP  [R402H16]  122.44 85.06 180 top
PR111  0R0402-PAD-1-GP  [0R0402-PAD]  123.45 85.06 0 top
PR112  2KR2F-3-GP  [R402H16]  120.05 84.84 90 top
PR113  20KR2F-L-GP  [R402H16]  120.05 83.82 270 top
PR114  35K7R2F-GP  [R402H16]  133.05 83.16 90 top
PR115  5K9R3F-3-GP  [R603H22]  119.67 82.68 270 top
PR116  47KR2F-GP  [R402H16]  122.84 82.52 270 top
PR117  100R2F-L1-GP-U  [R402H14]  120.81 81.53 270 top
PR118  0R0402-PAD-2-GP  [0R0402-PAD-1]  122.84 81.51 90 top
PR119  0R0402-PAD-2-GP  [0R0402-PAD-1]  116.44 84.12 0 top
PR120  2D2R5J-1-GP  [R805H24]  135.16 80.47 180 top
PR121  -  [0R0402-PAD]  133.23 80.34 270 top
PR122  10KR2F-2-GP  [R402H16]  119.92 80.11 270 top
PR123  100KR2F-L1-GP  [R402H16]  131.76 79.91 0 top
PR124  82KR2F-1-GP  [R402H16]  122.84 79.25 90 top
PR125  51R2F-2-GP  [R402H16]  119.92 79.1 90 top
PR126  2D2R5J-1-GP  [R805H24]  130.21 77.83 270 top
PR127  -  [0R0402-PAD]  116.47 79.35 0 top
PR128  100KR2F-L1-GP  [R402H16]  115.45 79.35 180 top
PR129  100KR2J-1-GP  [R402H16]  49.45 74.42 90 top
PR130  1MR2J-1-GP  [R402H16]  51.37 74.38 90 top
PR131  470KR2J-2-GP  [R402H16]  42.18 74.16 270 top
PR132  10KR2F-2-GP  [R402H16]  58.68 73.94 90 top
PR133  100KR2F-L1-GP  [R402H16]  58.66 72.85 270 top
PR134  680KR2F-GP  [R402H16]  47.25 71.87 180 top
PR135  -  [0R0402-PAD]  48.28 71.87 180 top
PR136  0R2J-2-GP  [R402H16]  61.42 71.74 180 top
PR137  2D2R5J-1-GP  [R805H24]  79.33 70.97 270 top
PR138  -  [0R0402-PAD]  59.93 70.97 180 top
PR139  -  [0R0805-PAD]  97.57 69.88 270 top
PR140  -  [0R0402-PAD]  53.88 69.09 270 top
PR141  -  [0R0805-PAD]  61.93 69.04 90 top
PR142  -  [0R0805-PAD]  97.59 67.89 270 top
PR143  -  [0R0805-PAD]  61.93 67.08 90 top
PR144  -  [0R0402-PAD]  45.93 66.98 0 top
PR145  D01R3721F-GP-U  [R3720H40]  37.04 66.05 180 top
PR146  -  [0R0805-PAD]  97.59 65.94 270 top
PR147  309KR2F-GP  [R402H16]  48.6 65.2 180 top
PR148  169KR2F-1-GP  [R402H16]  49.66 65.2 180 top
PR149  78K7R2F-GP  [R402H16]  50.71 65.2 0 top
PR150  10KR2J-3-GP  [R402H16]  60.5 64.59 270 top
PR151  -  [0R0805-PAD]  97.59 63.98 270 top
PR152  2D2R5J-1-GP  [R805H24]  63.86 63.91 180 top
PR153  3D3MR2J-GP  [R402H16]  48.38 63.7 90 top
PR154  102KR2F-GP  [R402H16]  50.71 63.26 180 top
PR155  88K7R2F-GP  [R402H16]  60.09 62.61 270 top
PR156  100KR2J-1-GP  [R402H16]  56.32 62.41 180 top
PR157  -  [0R0805-PAD]  97.59 62.03 270 top
PR158  15K4R2F-GP  [R402H16]  58.4 61.14 0 top
PR159  10KR2F-2-GP  [R402H16]  56.76 59.64 270 top
PR160  10KR2F-2-GP  [R402H16]  57.84 58.45 270 top
PR161  1D5R2F-GP  [R402H16]  43.21 57.78 270 top
PR162  6K65R2F-GP  [R402H16]  58.1 56.97 180 top
PR163  107KR2F-GP  [R402H16]  59.11 56.96 0 top
PR164  33KR2F-GP  [R402H16]  57.73 51.61 270 top
PR165  -  [0R0805-PAD]  98.13 54.53 270 top
PR166  -  [0R0402-PAD]  60.08 54.24 180 top
PR167  2D2R5J-1-GP  [R805H24]  63 54.08 180 top
PR168  2D2R5J-1-GP  [R805H24]  64.98 54.08 180 top
PR169  100KR2F-L1-GP  [R402H16]  59.63 52.7 90 top
PR170  -  [0R0805-PAD]  98.13 52.5 270 top
PR171  100KR2F-L1-GP  [R402H16]  59.63 51.61 90 top
PR172  -  [0R0805-PAD]  98.13 50.47 270 top
PR173  D01R3721F-GP-U  [R3720H40]  52.43 45.5 270 top
PR174  100KR2J-1-GP  [R402H16]  52.51 42.2 270 top
PR175  1KR2J-1-GP  [R402H16]  70.62 41.23 0 top
PR176  49K9R2F-L-GP  [R402H16]  51.56 41.16 270 top
PR177  10KR2F-2-GP  [R402H16]  51.56 40.13 270 top
PR178  3K3R6J-GP  [R1206H28]  69.23 32.57 90 top
PR179  47KR3J-L-GP  [R603H22]  66.55 28.91 90 top
PR180  240KR3-GP  [R603H22]  63.83 28.87 90 top
PR181  2D2R5F-2-GP  [R805H24]  56.8 221.62 180 bottom
PR182  2D2R5J-1-GP  [R805H24]  64.68 221.36 180 bottom
PR183  14KR2F-GP  [R402H16]  59.6 220.73 0 bottom
PR184  -  [0R0805-PAD]  73.57 220.22 180 bottom
PR185  -  [0R0805-PAD]  75.52 220.21 180 bottom
PR186  11KR2F-L-GP  [R402H16]  66.66 217.32 270 bottom
PR187  4K99R2F-L-GP  [R402H16]  51.47 216.41 270 bottom
PR188  10R2F-L-GP  [R402H14]  51.47 215.39 90 bottom
PR189  169R2F-GP  [R402H16]  69.12 214.76 180 bottom
PR190  -  [0R0402-PAD]  66.71 214.76 180 bottom
PR191  20R2F-GP  [R402H16]  66.96 213.23 270 bottom
PR192  95D3R2F-GP  [R402H16]  65.82 210.57 270 bottom
PR193  1R5J-2-GP  [R805H24]  71.36 209.85 180 bottom
PR194  2D2R5J-1-GP  [R805H24]  77.76 209.8 0 bottom
PR195  84D5R2F-L-GP  [R402H16]  66.56 209.22 270 bottom
PR196  10KR2J-3-GP  [R402H16]  71.79 207.01 180 bottom
PR197  1KR2F-3-GP  [R402H16]  54.77 206.63 270 bottom
PR198  0R0402-PAD-1-GP  [0R0402-PAD]  57.62 206.11 0 bottom
PR199  499R2F-2-GP  [R402H16]  59.66 206.11 0 bottom
PR200  14KR2F-GP  [R402H16]  62.56 205.16 180 bottom
PR201  7K5R3F-2-GP  [R603H22]  63.68 204.83 180 bottom
PR202  0R2J-2-GP  [R402H16]  56.5 203.35 0 bottom
PR203  1KR2J-1-GP  [R402H16]  66.01 203.71 0 bottom
PR204  100R2F-L1-GP-U  [R402H14]  58.2 202.69 90 bottom
PR205  NTC-100K-11-GP-U  [NTC-402H24-U]  71.97 200.94 180 bottom
PR206  0R2J-2-GP  [R402H16]  28.61 186.69 0 bottom
PR207  0R2J-2-GP  [R402H16]  29.55 186.8 180 top
PR208  1KR2J-1-GP  [R402H16]  30.02 184.06 270 bottom
PR209  1KR2J-1-GP  [R402H16]  30.47 182.58 0 bottom
PR210  2D2R5J-1-GP  [R805H24]  146.18 156.92 270 top
PR211  -  [0R0805-PAD]  146.95 143.43 270 bottom
PR212  5D1R3F-GP  [R603H22]  156.19 133.09 270 bottom
PR213  750KR2F-GP  [R402H16]  151.67 132.21 270 bottom
PR214  10KR2J-3-GP  [R402H16]  48.29 107.56 90 bottom
PR216  10KR2J-3-GP  [R402H16]  47.32 89.02 90 bottom
PR217  -  [0R0805-PAD]  61.9 68 270 bottom
PR218  120KR2F-L-GP  [R402H16]  46.4 66.13 0 bottom
PR219  -  [0R0805-PAD]  61.9 65.92 270 bottom
PR220  100KR2J-1-GP  [R402H16]  51.85 65.62 0 bottom
PR221  20R5F-1GP  [R805H24]  43.05 65.2 180 bottom
PR222  309KR3F-GP  [R603H22]  53.88 65.02 90 bottom
PR223  2D2R5J-1-GP  [R805H24]  77.15 63.68 90 bottom
PR224  47KR2F-GP  [R402H16]  53.63 62.87 270 bottom
PR225  100KR2F-L1-GP  [R402H16]  50.68 62.82 180 bottom
PR226  100KR2J-1-GP  [R402H16]  48.19 62.24 90 bottom
PR227  -  [0R0402-PAD]  53.63 60.71 270 bottom
PR228  100KR2J-1-GP  [R402H16]  55.91 59.56 270 bottom
PR229  33KR2F-GP  [R402H16]  53.12 56.39 0 bottom
PR230  -  [0R0805-PAD]  98.15 54.53 90 bottom
PR231  100KR2J-1-GP  [R402H16]  52.99 54.36 0 bottom
PR232  10KR2F-2-GP  [R402H16]  51.85 54.36 180 bottom
PR233  10R2F-L-GP  [R402H14]  47.87 53.2 180 bottom
PR234  7D5R2F-GP  [R402H16]  48.97 53.19 180 bottom
PR235  -  [0R0805-PAD]  98.13 52.5 90 bottom
PR236  -  [0R0402-PAD]  45.04 16.23 180 bottom
PR237  -  [0R0402-PAD]  44 16.23 180 bottom
PR238  -  [0R0402-PAD]  43.04 13.61 180 bottom
PR239  -  [0R0402-PAD]  41.97 13.61 180 bottom
PR240  -  [0R0805-PAD]  47.07 160.4 90 top
PR242  0R0402-PAD-1-GP  [0R0402-PAD]  77.4 175.12 180 bottom
PR243  -  [0R0402-PAD]  31.2 187.96 270 top
PRB1  261KR2F-GP  [R402H16]  155.86 134.75 270 bottom
PRT1  -  [0R0805-PAD]  145.58 144.02 180 top
PRT2  -  [0R0805-PAD]  147.61 144.02 180 top
PRT3  2D2R5J-1-GP  [R805H24]  80.4 59.61 270 top
PT1  SE47U25VM-13-GP  [SE361414H241]  40.52 211.18 270 top
PT2  SE390U2D5VM-9-GP  [SE361414H241]  61.74 196.3 180 top
PT3  E820U2D5VM-6-GP  [ECAP-100D6D3H375]  109 100.28 0 top
PT4  SE47U25VM-13-GP  [SE361414H241]  143.34 97.36 180 top
PT5  E820U2D5VM-6-GP  [ECAP-100D6D3H375]  109 92.41 0 top
PT6  SE47U25VM-13-GP  [SE361414H241]  70.07 64.98 180 top
PT7  SE220U6D3VM-3GP  [SE3116H241]  91.99 63.85 0 top
PT8  SE220U6D3VM-3GP  [SE3116H241]  92.26 54.71 180 top
PTC1  E820U2D5VM-6-GP  [ECAP-100D6D3H375]  148.34 162.05 270 top
PU1  APL5930KAI-TRG-1-GP  [SOIC8-G3530H63]  26.94 192.21 180 top
PU2  RT8068AZQWID-GP-U  [DFN10G3-G265175H32]  28.54 179.03 270 top
PU3  RT8068AZQWID-GP-U  [DFN10G3-G265175H32]  33.62 165.58 270 top
PU4  RT8068AZQWID-GP-U  [DFN10G3-G265175H32]  30.46 151.13 270 top
PU5  RT8231AGQW-GP  [QFN20-G1D75H32]  151.7 133.88 90 top
PU6  APL5930KAI-TRG-1-GP  [SOIC8-G3530H63]  115.27 111.07 270 top
PU7  NTMFS4C06NT1G-GP  [PTDS08-1H44]  130.54 102.39 90 top
PU8  NTMFS4C10NT1G-GP  [PTDS08-1H44]  132.44 93.73 270 top
PU9  AO4407AL-GP  [SOIC8H69]  38.15 70.81 90 top
PU10  RT6575DGQW-GP  [QFN20-G1D75H32]  62.16 59.56 90 top
PU11  AO4407AL-GP  [SOIC8H69]  58.53 43.12 270 top
PU12  AO4407AL-GP  [SOIC8H69]  65.46 39.03 0 top
PU13  NCP81226MNTXG-GP  [LFQFN52J6-G4D8-1H40]  60.95 213.66 270 bottom
PU14  AON7410-GP  [PPAK-8P-3232H36]  74.58 211.46 180 bottom
PU15  AON7506-GP  [PPAK-8P-3232H36]  80.93 209.93 0 bottom
PU16  NTMFS4C06NT1G-GP  [PTDS08-1H44]  130.55 102.4 270 bottom
PU17  NTMFS4C10NT1G-GP  [PTDS08-1H44]  132.24 93.73 90 bottom
PU18  AON7410-GP  [PPAK-8P-3232H36]  40.07 56.34 180 bottom
PU19  AON7410-GP  [PPAK-8P-3232H36]  35.66 54.84 0 bottom
PWRCN1  ACES-CON10-30-GP  [51530-01041-W01]  26.75 22.5 270 top
Q1  DMN5L06K-7-GP  [SOT23DGS2D4H48]  103.46 223.18 180 top
Q2  DMN5L06K-7-GP  [SOT23DGS2D4H48]  10.29 221.42 90 top
Q3  AO3418L-GP  [SOT23DGS2D8H50]  146.31 220.04 90 top
Q4  DMN5L06K-7-GP  [SOT23DGS2D4H48]  14.11 219.3 270 top
Q5  DMN5L06K-7-GP  [SOT23DGS2D4H48]  83.87 218.75 180 top
Q6  2N7002EDW-2-GP  [SOT-363H44]  151.97 209.55 90 top
Q7  MMBT3906-4-GP  [SOT23CBE2D4H44]  157.12 178.66 90 top
Q8  2N7002A-7-GP  [SOT23DGS2D4H48]  56.55 177.42 270 top
Q9  2N7002KDW-1-GP  [SOT-363H44]  41.67 158.04 270 top
Q10  2N7002A-7-GP  [SOT23DGS2D4H48]  59.29 147.44 0 top
Q11  LMBT3904LT1G-GP  [SOT23CBE2D4H44]  146.49 126.77 90 top
Q12  2N7002EDW-2-GP  [SOT-363H44]  78.9 121.33 270 top
Q13  2N7002EDW-2-GP  [SOT-363H44]  82.58 121.33 270 top
Q14  2N7002H-GP  [SOT23DGS2D4H44]  137.25 119.09 90 top
Q15  2N7002H-GP  [SOT23DGS2D4H44]  133.39 119.08 270 top
Q16  2N7002H-GP  [SOT23DGS2D4H44]  129.47 119.07 270 top
Q17  2N7002H-GP  [SOT23DGS2D4H44]  123.2 119.16 90 top
Q18  LMBT3904LT1G-GP  [SOT23CBE2D4H44]  118.44 118.98 90 top
Q19  2N7002KDW-GP  [SOT-363H44]  146.21 118.37 180 top
Q20  LMBT3904LT1G-GP  [SOT23CBE2D4H44]  82.73 117.66 0 top
Q21  LMBT3904LT1G-GP  [SOT23CBE2D4H44]  86.6 117.66 0 top
Q22  2N7002A-7-GP  [SOT23DGS2D4H48]  90.25 117.63 0 top
Q23  DMN5L06K-7-GP  [SOT23DGS2D4H48]  93.86 117.63 0 top
Q24  2N7002H-GP  [SOT23DGS2D4H44]  144.22 108.66 0 top
Q25  2N7002K-2-GP  [SOT23DGS2D4H44]  102.45 97.56 270 top
Q26  2N7002A-7-GP  [SOT23DGS2D4H48]  107.48 83.95 0 top
Q27  AO3413L-GP  [SOT23DGS2D8H50]  111.03 84.33 0 top
Q28  2N7002KDW-1-GP  [SOT-363H44]  100.74 81.38 0 top
Q29  AZ5125-02S-R7G-GP  [SOT23-2D4-312H46]  167.49 78.5 90 top
Q30  MMBT3904DW-GP  [SOT-363H44]  50.4 77.85 90 top
Q31  MMBT3904DW-GP  [SOT-363H44]  62.19 76.96 270 top
Q32  2N7002KDW-1-GP  [SOT-363H44]  140.81 75.95 90 top
Q33  AZ5125-02S-R7G-GP  [SOT23-2D4-312H46]  167.49 74.56 90 top
Q34  2N7002K-2-GP  [SOT23DGS2D4H44]  129.62 72.44 180 top
Q35  2N7002A-7-GP  [SOT23DGS2D4H48]  151.37 47.85 90 top
Q36  2N7002KDW-1-GP  [SOT-363H44]  68.89 44.81 270 top
Q37  AZ5125-02S-R7G-GP  [SOT23-2D4-312H46]  84.92 37.08 270 top
Q38  2N7002K-2-GP  [SOT23DGS2D4H44]  93.43 36.86 270 top
Q39  MMBT3904-4-GP  [SOT23CBE2D4H44]  46.67 25.02 0 top
Q40  LMBT3904LT1G-GP  [SOT23CBE2D4H44]  41.18 24.89 0 top
Q41  2N7002A-7-GP  [SOT23DGS2D4H48]  46.08 19.2 270 top
Q42  LMBT3904LT1G-GP  [SOT23CBE2D4H44]  30.56 15.21 90 top
Q43  MMBT3904-4-GP  [SOT23CBE2D4H44]  42.98 8.27 0 top
Q44  MMBT3904-4-GP  [SOT23CBE2D4H44]  47.66 6.93 0 top
Q45  2N7002KDW-GP  [SOT-363H44]  87.04 221.75 180 bottom
Q46  2N7002KDW-GP  [SOT-363H44]  83.83 221.72 0 bottom
Q47  2N7002KDW-GP  [SOT-363H44]  80.66 221.72 0 bottom
Q48  LMBT3904LT1G-GP  [SOT23CBE2D4H44]  131.33 218.16 270 bottom
Q49  LMBT3904LT1G-GP  [SOT23CBE2D4H44]  105.29 215.96 0 bottom
Q50  2N7002A-7-GP  [SOT23DGS2D4H48]  131.35 214.5 270 bottom
Q51  AO3413L-GP  [SOT23DGS2D8H50]  127.16 210.06 0 bottom
Q52  2N7002KDW-GP  [SOT-363H44]  27.47 170.05 90 bottom
Q53  MMBT3904-4-GP  [SOT23CBE2D4H44]  141.3 138.83 0 bottom
Q55  2N7002A-7-GP  [SOT23DGS2D4H48]  41.9 117.07 180 bottom
Q56  2N7002A-7-GP  [SOT23DGS2D4H48]  45.49 116.94 0 bottom
Q59  AO3413L-GP  [SOT23DGS2D8H50]  42.5 110.26 180 bottom
Q60  2N7002KDW-1-GP  [SOT-363H44]  47.62 76.73 0 bottom
Q61  2N7002KDW-1-GP  [SOT-363H44]  37.04 76.1 270 bottom
Q62  2N7002KDW-1-GP  [SOT-363H44]  32.57 75.59 270 bottom
Q63  DMP2130L-7-GP  [SOT23DGS2D4H48]  136.86 75.3 270 bottom
Q64  2N7002K-2-GP  [SOT23DGS2D4H44]  136.87 71.68 270 bottom
Q65  LMBT3906LT1G-1-GP  [SOT23CBE2D4H44]  130.86 67.97 0 bottom
Q66  2N7002-11-GP  [SOT23DGS2D4H44]  154.82 58.19 0 bottom
Q67  LMBT3904LT1G-GP  [SOT23CBE2D4H44]  149.94 49.25 180 bottom
Q68  AO4286-GP  [SOIC8H69]  35.72 39.8 270 bottom
Q69  MMBT3904DW-GP  [SOT-363H44]  149.05 39.09 270 bottom
Q70  2N7002A-7-GP  [SOT23DGS2D4H48]  145.37 38.73 0 bottom
Q71  2N7002A-7-GP  [SOT23DGS2D4H48]  127.39 24.31 90 bottom
Q72  2N7002A-7-GP  [SOT23DGS2D4H48]  23.93 21.23 90 bottom
Q73  DMN5L06K-7-GP  [SOT23DGS2D4H48]  43.82 23.39 0 bottom
Q74  2N7002A-7-GP  [SOT23DGS2D4H48]  27.82 20.02 90 bottom
Q75  MMBT3904-4-GP  [SOT23CBE2D4H44]  23.93 17.63 270 bottom
Q76  MMBT3904DW-GP  [SOT-363H44]  31.22 17.17 180 bottom
Q77  MMBT3904-4-GP  [SOT23CBE2D4H44]  27.8 16.41 270 bottom
Q78  MMBT3904-4-GP  [SOT23CBE2D4H44]  23.96 14.02 90 bottom
Q79  AO3413L-GP  [SOT23DGS2D8H50]  31.48 9.47 90 bottom
Q80  MMBT3904-4-GP  [SOT23CBE2D4H44]  43.09 6.99 0 bottom
Q81  LMBT3904LT1G-GP  [SOT23CBE2D4H44]  161.14 128.9 0 bottom
Q1801  2N7002K-2-GP  [SOT23DGS2D4H44]  140.28 88.12 0 top
Q1802  MMBT2222A-5-GP  [SOT23CBE2D4H44]  128.15 74.07 90 bottom
Q2801  2N7002A-7-GP  [SOT23DGS2D4H48]  140.06 41.33 90 top
Q4501  2N7002A-7-GP  [SOT23DGS2D4H48]  139.28 81.74 0 top
Q9201  DMN5L06K-7-GP  [SOT23DGS2D4H48]  141.64 47.96 270 top
Q9202  DMN5L06K-7-GP  [SOT23DGS2D4H48]  141.66 53.7 270 top
R1  2K2R2J-2-GP  [R402H16]  106.39 225.16 270 top
R2  4K7R2J-2-GP  [R402H16]  148.47 223.77 180 top
R3  10KR2J-3-GP  [R402H16]  34.41 222.81 90 top
R4  0R0402-PAD-1-GP  [0R0402-PAD]  32.41 222.8 90 top
R7  10R2J-2-GP  [R402H14]  83.35 222.25 90 top
R9  1KR2J-1-GP  [R402H16]  127.16 221.5 270 top
R10  0R2J-2-GP  [R402H16]  122.08 221.49 270 top
R11  10KR2J-3-GP  [R402H16]  83.35 221.23 270 top
R12  1KR2J-1-GP  [R402H16]  128.78 221.04 0 top
R13  0R2J-2-GP  [R402H16]  122.08 220.47 270 top
R14  0R0402-PAD-1-GP  [0R0402-PAD]  127.15 220.41 90 top
R16  0R0402-PAD-2-GP  [0R0402-PAD-1]  35.02 220.31 180 top
R17  0R2J-2-GP  [R402H16]  36.15 220.3 180 top
R18  0R2J-2-GP  [R402H16]  19.08 219.98 270 top
R19  0R2J-2-GP  [R402H16]  122.08 219.46 270 top
R20  10KR2J-3-GP  [R402H16]  104.18 219.25 270 top
R21  0R2J-2-GP  [R402H16]  19.09 218.93 270 top
R22  0R2J-2-GP  [R402H16]  32.91 218.86 0 top
R23  0R2J-2-GP  [R402H16]  33.98 218.86 0 top
R24  0R0402-PAD-2-GP  [0R0402-PAD-1]  105.8 218.58 180 top
R25  0R2J-2-GP  [R402H16]  122.08 218.44 270 top
R26  0R2J-2-GP  [R402H16]  104.17 218.19 270 top
R27  100KR2J-1-GP  [R402H16]  17.17 217.74 90 top
R28  1KR2J-1-GP  [R402H16]  19.14 217.73 270 top
R29  0R2J-2-GP  [R402H16]  122.13 217.4 270 top
R30  0R0402-PAD-2-GP  [0R0402-PAD-1]  104.17 217.17 90 top
R31  0R0402-PAD-1-GP  [0R0402-PAD]  18.83 216.55 270 top
R32  0R2J-2-GP  [R402H16]  83.56 216.25 90 top
R33  0R0402-PAD-2-GP  [0R0402-PAD-1]  104.17 216.15 270 top
R34  0R2J-2-GP  [R402H16]  85.43 215.67 0 top
R35  1KR2J-1-GP  [R402H16]  18.83 215.48 270 top
R36  0R0402-PAD-2-GP  [0R0402-PAD-1]  104.17 215.14 270 top
R37  0R0402-PAD-2-GP  [0R0402-PAD-1]  104.17 214.12 270 top
R38  1KR2J-1-GP  [R402H16]  33.25 213.82 180 top
R39  0R0402-PAD-1-GP  [0R0402-PAD]  85.46 213.67 0 top
R40  0R0402-PAD-1-GP  [0R0402-PAD]  19.11 213.44 270 top
R41  10KR2J-3-GP  [R402H16]  149.29 213.17 270 top
R42  0R0402-PAD-2-GP  [0R0402-PAD-1]  104.17 213.11 270 top
R43  1KR2J-1-GP  [R402H16]  33.69 212.35 270 top
R44  100KR2J-1-GP  [R402H16]  149.29 212.13 270 top
R45  0R0402-PAD-2-GP  [0R0402-PAD-1]  104.17 212.09 270 top
R46  1KR2J-1-GP  [R402H16]  85.48 211.65 180 top
R47  -  [0R0805-PAD]  17.71 211.63 90 top
R48  1KR2J-1-GP  [R402H16]  33.7 211.28 90 top
R49  0R0402-PAD-2-GP  [0R0402-PAD-1]  104.17 211.07 270 top
R50  47KR2J-2-GP  [R402H16]  149.19 210.95 90 top
R51  10KR2J-3-GP  [R402H16]  33.68 210.23 270 top
R52  0R0402-PAD-2-GP  [0R0402-PAD-1]  155.3 209.99 0 top
R53  100KR2J-1-GP  [R402H16]  149.19 209.62 90 top
R54  33R2J-2-GP  [R402H16]  103.39 208.38 180 top
R55  0R0402-PAD-2-GP  [0R0402-PAD-1]  32.43 208.17 180 top
R56  10KR2J-3-GP  [R402H16]  18.53 207.51 270 top
R57  100KR2J-1-GP  [R402H16]  152.6 207.45 270 top
R58  4K7R2J-2-GP  [R402H16]  16.75 207.01 0 top
R59  10KR2J-3-GP  [R402H16]  87.51 207.01 0 top
R60  10R2J-2-GP  [R402H14]  88.63 207.01 180 top
R61  10R2J-2-GP  [R402H14]  90.08 207.01 180 top
R62  10R2J-2-GP  [R402H14]  91.22 207.01 0 top
R63  10R2J-2-GP  [R402H14]  92.36 207.01 0 top
R64  10R2J-2-GP  [R402H14]  93.51 207.01 0 top
R65  10R2J-2-GP  [R402H14]  94.65 207.01 0 top
R66  10R2J-2-GP  [R402H14]  95.79 207.01 0 top
R67  10R2J-2-GP  [R402H14]  96.93 207.01 0 top
R68  10R2J-2-GP  [R402H14]  98.08 207.01 0 top
R69  10R2J-2-GP  [R402H14]  99.22 207.01 0 top
R70  10R2J-2-GP  [R402H14]  100.31 206.98 180 top
R71  8K2R2F-1-GP  [R402H16]  17.18 205.51 270 top
R72  20KR2J-L2-GP  [R402H16]  19.21 205.49 270 top
R73  2K2R2J-2-GP  [R402H16]  15.68 203.3 0 top
R74  33R2J-2-GP  [R402H16]  105.94 203.25 270 top
R75  10KR2J-3-GP  [R402H16]  121.54 203.13 0 top
R76  0R0402-PAD-2-GP  [0R0402-PAD-1]  20.18 202.77 180 top
R77  0R0402-PAD-2-GP  [0R0402-PAD-1]  91.8 201.66 0 top
R78  0R0402-PAD-2-GP  [0R0402-PAD-1]  107.33 201.43 270 top
R79  100R2F-L1-GP-U  [R402H14]  15.7 201.35 180 top
R80  0R0402-PAD-1-GP  [0R0402-PAD]  93.08 200.77 0 top
R81  33R2J-2-GP  [R402H16]  113.07 200.24 270 top
R82  33R2J-2-GP  [R402H16]  111.1 199.67 0 top
R83  249R2F-GP  [R402H16]  109.01 199.67 180 top
R84  33R2J-2-GP  [R402H16]  107.93 199.66 0 top
R85  0R2J-2-GP  [R402H16]  106.87 199.66 0 top
R86  499R2F-2-GP  [R402H16]  110.06 199.66 0 top
R87  33R2J-2-GP  [R402H16]  113.09 199.14 270 top
R88  10KR2J-L-GP  [R402H15]  69.48 197.49 90 top
R89  100KR2J-1-GP  [R402H16]  72.58 197.13 0 top
R90  0R0402-PAD-1-GP  [0R0402-PAD]  145.83 194.72 90 top
R91  -  [0R0402-PAD]  156.9 192.98 0 top
R92  10KR2J-3-GP  [R402H16]  155.36 192.55 90 top
R93  68R2F-GP  [R402H16]  160.47 190.04 270 top
R94  0R0402-PAD-1-GP  [0R0402-PAD]  145.77 189.33 90 top
R95  10MR3F-GP  [R603H22]  75.59 188.49 0 top
R96  0R0402-PAD-1-GP  [0R0402-PAD]  145.13 186.87 0 top
R97  22R2J-2-GP  [R402H16]  80.36 186.45 180 top
R98  22R2J-2-GP  [R402H16]  81.4 186.45 180 top
R99  -  [0R0402-PAD]  147.4 186.08 90 top
R100  NTC-100K-8-GP  [NTC-603H38]  48.7 185.91 270 top
R101  10KR2F-2-GP  [R402H16]  67.99 185.86 0 top
R102  4K7R2F-GP  [R402H16]  69.23 185.84 0 top
R103  10KR2F-2-GP  [R402H16]  71.52 185.84 0 top
R104  10KR2F-2-GP  [R402H16]  72.64 185.84 0 top
R105  10KR2F-2-GP  [R402H16]  70.4 185.83 0 top
R106  10KR2J-3-GP  [R402H16]  74.86 185.83 0 top
R108  0R0402-PAD-1-GP  [0R0402-PAD]  78.29 185.74 0 top
R109  10KR2J-3-GP  [R402H16]  147.41 185.02 90 top
R110  0R0402-PAD-1-GP  [0R0402-PAD]  77.25 185.15 0 top
R111  33R2J-2-GP  [R402H16]  65.69 184.15 90 top
R112  10KR2F-2-GP  [R402H16]  69.23 183.81 0 top
R113  4K7R2F-GP  [R402H16]  68.19 183.8 0 top
R114  4K7R2F-GP  [R402H16]  73.77 183.83 0 top
R115  4K7R2F-GP  [R402H16]  71.82 183.78 0 top
R116  4K7R2F-GP  [R402H16]  70.69 183.78 0 top
R117  33R2J-2-GP  [R402H16]  65.69 183.13 90 top
R118  10KR2F-2-GP  [R402H16]  29.12 182.88 0 top
R119  0R2J-2-GP  [R402H16]  27.99 182.86 180 top
R120  0R0402-PAD-2-GP  [0R0402-PAD-1]  154.16 182.31 90 top
R121  38K3R2F-GP  [R402H16]  25.48 182.15 270 top
R122  33R2J-2-GP  [R402H16]  65.69 182.12 90 top
R123  33R2J-2-GP  [R402H16]  65.69 181.1 90 top
R124  0R0402-PAD-2-GP  [0R0402-PAD-1]  157.69 181.59 0 top
R125  4K7R2F-GP  [R402H16]  156.57 181.58 0 top
R126  20KR2F-L-GP  [R402H16]  154.16 180.34 270 top
R127  0R2J-2-GP  [R402H16]  63.74 180.27 270 top
R128  51KR2F-L-GP  [R402H16]  23.97 180.11 270 top
R129  0R2J-2-GP  [R402H16]  66.17 180.06 90 top
R130  0R0402-PAD-1-GP  [0R0402-PAD]  49.51 179.1 180 top
R131  10KR2F-2-GP  [R402H16]  51.09 179.83 90 top
R132  1MR2J-1-GP  [R402H16]  55.53 179.83 90 top
R133  10KR2J-3-GP  [R402H16]  57.56 179.83 90 top
R134  0R2J-2-GP  [R402H16]  63.74 179.23 270 top
R135  0R2J-2-GP  [R402H16]  66.17 179.02 90 top
R136  0R2J-2-GP  [R402H16]  59.98 177.67 270 top
R137  4K7R2F-GP  [R402H16]  62.52 177.67 90 top
R138  4K7R2F-GP  [R402H16]  65.69 177.67 90 top
R139  4K7R2F-GP  [R402H16]  154.21 177.67 270 top
R140  1KR2J-1-GP  [R402H16]  154.25 176.56 90 top
R141  0R0402-PAD-2-GP  [0R0402-PAD-1]  51.99 175.7 90 top
R142  -  [0R0402-PAD]  59.9 175.11 90 top
R143  0R0402-PAD-2-GP  [0R0402-PAD-1]  154.26 174.59 90 top
R144  4K7R2F-GP  [R402H16]  63.28 174.37 90 top
R145  4K7R2F-GP  [R402H16]  65.18 174.37 90 top
R146  1KR2J-1-GP  [R402H16]  158.56 174.33 90 top
R147  4K7R2F-GP  [R402H16]  63.28 173.35 90 top
R148  10KR2F-2-GP  [R402H16]  65.18 173.35 90 top
R149  100KR2J-1-GP  [R402H16]  59.17 173.34 270 top
R150  0R0402-PAD-2-GP  [0R0402-PAD-1]  156.43 173.27 90 top
R151  0R0402-PAD-2-GP  [0R0402-PAD-1]  47.73 173.21 0 top
R152  0R0402-PAD-2-GP  [0R0402-PAD-1]  49.05 173.21 0 top
R153  0R0402-PAD-2-GP  [0R0402-PAD-1]  50.38 173.21 0 top
R154  0R2J-2-GP  [R402H16]  154.87 172.66 180 top
R155  -  [0R0402-PAD]  59.17 172.31 90 top
R156  20KR2F-L-GP  [R402H16]  156.43 172.21 270 top
R157  4K7R2F-GP  [R402H16]  63.28 172.09 90 top
R158  4K7R2F-GP  [R402H16]  65.18 172.09 90 top
R159  10KR2J-3-GP  [R402H16]  61.33 172.06 90 top
R160  4K7R2F-GP  [R402H16]  63.28 170.94 90 top
R161  10KR2F-2-GP  [R402H16]  65.18 170.94 90 top
R162  4K7R2F-GP  [R402H16]  59.71 170.52 0 top
R163  4K7R2F-GP  [R402H16]  61.23 170.44 90 top
R164  0R0402-PAD-1-GP  [0R0402-PAD]  55.41 169.91 270 top
R165  54K9R2F-L-GP  [R402H16]  31.4 169.04 0 top
R166  10KR2J-3-GP  [R402H16]  55.39 168.81 90 top
R167  51KR2F-L-GP  [R402H16]  29.58 166.91 270 top
R168  0R0402-PAD-2-GP  [0R0402-PAD-1]  56.04 163.83 90 top
R169  68R2F-GP  [R402H16]  53.5 162.05 90 top
R170  220R2F-GP  [R402H16]  57.06 161.93 90 top
R171  51R2J-2-GP  [R402H16]  67.52 159.77 90 top
R172  1KR2J-1-GP  [R402H16]  45.53 158.74 270 top
R173  1KR2J-1-GP  [R402H16]  48.83 157.78 270 top
R174  200KR2F-L-GP  [R402H16]  64.67 157.23 180 top
R175  0R0402-PAD-1-GP  [0R0402-PAD]  162.24 158.01 90 top
R176  10R2F-L-GP  [R402H14]  160.74 153.58 180 top
R177  100KR2F-L1-GP  [R402H16]  59.03 151 90 top
R178  10R2F-L-GP  [R402H14]  160.75 150.72 180 top
R179  10KR2J-3-GP  [R402H16]  59.03 149.85 270 top
R180  10R2F-L-GP  [R402H14]  160.75 148.65 0 top
R181  402R2F-GP  [R402H16]  82.46 146.48 0 top
R182  402R2F-GP  [R402H16]  84.31 146.58 0 top
